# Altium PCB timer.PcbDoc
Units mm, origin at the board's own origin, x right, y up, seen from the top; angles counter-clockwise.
Board outline 237.64 x 122.94 mm, 2 copper layers (Top Layer, Bottom Layer); 21 components, 58 nets, 170 pads, 28 vias.
Unrouted connection lines stored in the file: 1.
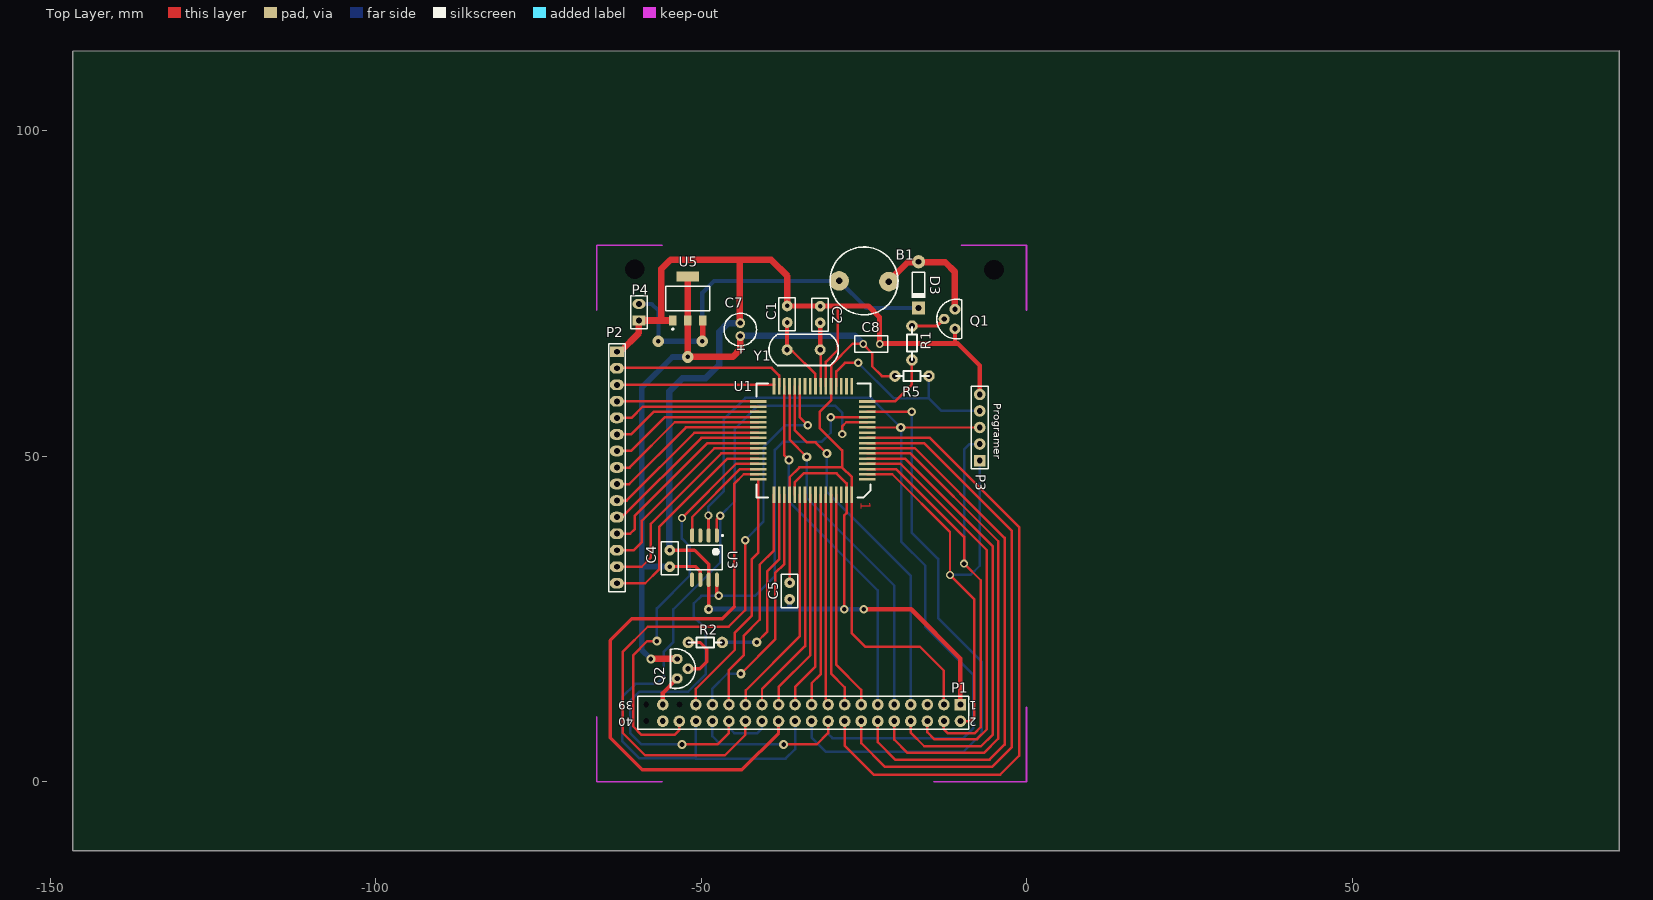
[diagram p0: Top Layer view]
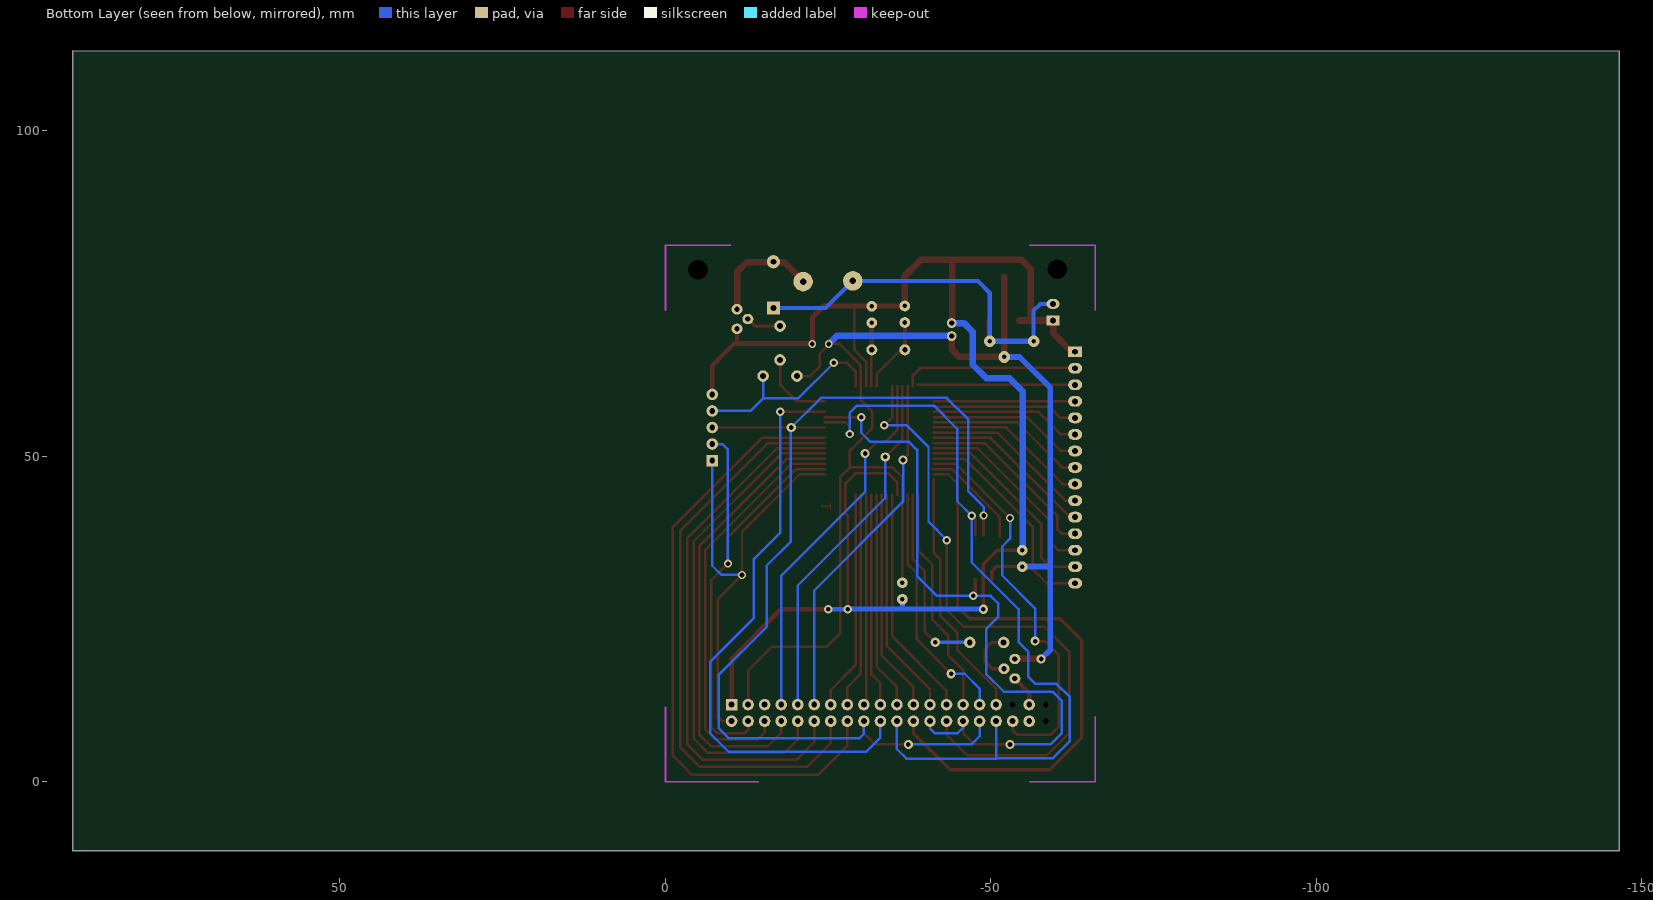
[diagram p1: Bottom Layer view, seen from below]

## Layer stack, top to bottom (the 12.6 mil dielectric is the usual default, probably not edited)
Top Layer: signal copper 0.0356
Dielectric: dielectric 0.32, FR-4, Dk 4.8
Bottom Layer: signal copper 0.0356

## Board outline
91.034,112.344 91.034,-10.592 91.059,-10.566 91.084,-10.566 -146.507,-10.566 -146.507,112.192 -146.558,112.243

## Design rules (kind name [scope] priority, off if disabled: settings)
Clearance [All] p1: gap=0.25
ComponentClearance [All] p1 off: gap=0.254 collisioncheckmode=3 verticalgap=2540 showdistances=FALSE
HoleSize [All] p1: absolutevalues=TRUE maxlimit=5 minlimit=0.025 maxpercent=80.000 minpercent=20.000
PolygonConnect [All] p1: connectstyle=Relief reliefconductorwidth=0.254 reliefentries=4 polygonreliefangle="90 Angle"
RoutingVias [All] p1: holewidth=0.711 width=1.27 viastyle="Through Hole" minholewidth=0.711 minwidth=1.27 maxholewidth=0.711 maxwidth=3
SolderMaskExpansion [All] p1: expansion=0.102
TestPointUsage [All] p1: valid=0 allowmultiple=FALSE
Testpoint [All] p1: side=15 testpointundercomponent=TRUE minsize=1.016 maxsize=2.54 preferedsize=1.524 minholesize=0 maxholesize=1.016 preferedholesize=0.813 testpointgrid=0.025 style=1023 order=0123456789
Width [All] p1: maxlimit=2.54 minlimit=0.254 preferedwidth=0.254 toplayer_minwidth=0.381 toplayer_prefwidth=0.381 bottomlayer_minwidth=0.381 bottomlayer_prefwidth=0.381 minimp=50.000000 maximp=50.000000 favimp=50.000000
17 further rules are at their usual default settings.

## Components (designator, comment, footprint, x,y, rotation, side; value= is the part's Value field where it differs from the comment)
B1 "Speaker" BUZZER -23.698,76.962 r0 top (schematic designator BUZZER1)
C1 "Cap" RAD-0.1#1 -36.779,71.831 r270 top
C2 "Cap" RAD-0.1#1 -31.699,71.78 r270 top
C4 "Cap" RAD-0.1#1 -54.813,34.315 r270 top
C5 "Cap" RAD-0.1#1 -36.398,29.312 r90 top
C7 "Cap Pol1" C100U -44.272,68.834 r270 top
C8 "Cap" RAD-0.1#2 -23.825,67.259 r180 top
D3 "Diode 1N4007" DO-35 -16.586,76.352 r270 top
P1 "TFT LCD Header" HDR2X20 -10.16,11.862 r180 top
P2 "Header 15" HDR1X15 -62.941,66.065 r270 top
P3 "Programer Header" HDR1X5 -7.188,49.352 r90 top
P4 "input" HDR1X2 -59.538,70.869 r90 top
Q1 "2N3904" TO92B -10.998,71.095 r90 top
Q2 "2N3906" TO92B -53.67,17.374 r270 top
R1 "Res1" Res0.125W -17.602,67.412 r90 top
R2 "Res1" Res0.125W -49.352,21.412 r0 top
R5 "Res1" Res0.125W -17.602,62.332 r180 top
U1 "ATmega64L-8AI" "ATMEL TQFP64" -32.842,52.451 r180 top
U3 "AT45DB161D-SU" 8S2_N -49.479,34.442 r270 top
U5 "REG1117-3.3" ZZ311 -52.045,74.244 r0 top
Y1 "" XTAL -34.239,66.37 r0 top

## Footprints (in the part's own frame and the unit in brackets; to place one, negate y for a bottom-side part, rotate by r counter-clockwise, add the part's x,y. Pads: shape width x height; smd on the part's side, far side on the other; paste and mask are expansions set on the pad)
8S2_N [mm] "SOP, 8-Leads, Body 5.3x5.3mm, Pitch 1.27mm, IPC Medium Density"
  oval 2.2x0.6 smd: 1(-3.4,1.905) 2(-3.4,0.635) 3(-3.4,-0.635) 4(-3.4,-1.905) 5(3.4,-1.905) 6(3.4,-0.635) 7(3.4,0.635) 8(3.4,1.905)
  silkscreen extent -3.52,-2.75 1.9,2.88, body extent -2.73,-2.75 2.73,2.75, height 2.03
"ATMEL TQFP64" [mm]
  rect 2.54x0.406 smd: 1(-8.366,5.982) 2(-8.366,5.194) 3(-8.366,4.407) 4(-8.366,3.594) 5(-8.366,2.807) 6(-8.366,1.994) 7(-8.366,1.206) 8(-8.366,0.419) 9(-8.366,-0.394) 10(-8.366,-1.181) 11(-8.366,-1.994) 12(-8.366,-2.781) 13(-8.366,-3.569) 14(-8.366,-4.382) 15(-8.366,-5.169) 16(-8.366,-5.982) 33(8.348,-5.982) 34(8.348,-5.169) 35(8.348,-4.382) 36(8.348,-3.569) 37(8.348,-2.781) 38(8.348,-1.994) 39(8.348,-1.181) 40(8.348,-0.394) 41(8.348,0.419) 42(8.348,1.206) 43(8.366,2) 44(8.348,2.807) 45(8.348,3.594) 46(8.348,4.407) 47(8.348,5.194) 48(8.348,5.982)
  rect 0.406x2.54 smd: 17(-6.003,-8.344) 18(-5.191,-8.344) 19(-4.403,-8.344) 20(-3.616,-8.344) 21(-2.803,-8.344) 22(-2.016,-8.344) 23(-1.203,-8.344) 24(-0.415,-8.344) 25(0.372,-8.344) 26(1.185,-8.344) 27(1.972,-8.344) 28(2.785,-8.344) 29(3.572,-8.344) 30(4.36,-8.344) 31(5.173,-8.344) 32(5.96,-8.344) 49(5.96,8.344) 50(5.173,8.344) 51(4.36,8.344) 52(3.572,8.344) 53(2.785,8.344) 54(1.972,8.344) 55(1.185,8.344) 56(0.372,8.344) 57(-0.415,8.344) 58(-1.203,8.344) 59(-2.016,8.344) 60(-2.803,8.344) 61(-3.616,8.344) 62(-4.403,8.344) 63(-5.191,8.344) 64(-6.003,8.344)
  silkscreen extent -8.87,-8.75 8.65,8.78
BUZZER [mm]
  round 3 hole 1: 1(-5.08,0) 2(2.54,-0.127)
  silkscreen extent -6.47,-5.21 3.94,5.21
C100U [mm]
  round 1.5 hole 0.8: 1(0.36,0.3) 2(-1.64,0.3)
  silkscreen extent -3.14,-2.2 1.86,2.8
DO-35 [mm] "Diode, Axial; Body 3.8 x 1.9 mm (LxDia. max), Lead Dia. 0.53 mm (max)"
  round 2.032 hole 0.9: 1(-3.55,0)
  rect 2.032x2.032 hole 0.9: 2(3.55,0)
  silkscreen extent -1.95,-0.95 2.05,0.95
HDR1X2 [mm] "Connector; Header; 2 Position"
  rect 1.5x2 hole 0.9: 1(0,0)
  oval 1.5x2 hole 0.9: 2(2.54,0)
  silkscreen extent -1.27,-1.27 3.81,1.27
HDR1X5 [mil] "Connector; Header; 5 Position"
  rect 70x70 hole 35.43: 1(0,0)
  round 70 hole 35.43: 2(100,0) 3(200,0) 4(300,0) 5(400,0)
  silkscreen extent -50,-50 450,50
HDR1X15 [mil] "Connector; Header; 15 Position"
  rect 65x85 hole 35.43: 1(0,0)
  oval 65x85 hole 35.43: 2(100,0) 3(200,0) 4(300,0) 5(400,0) 6(500,0) 7(600,0) 8(700,0) 9(800,0) 10(900,0) 11(1000,0) 12(1100,0) 13(1200,0) 14(1300,0) 15(1400,0)
  silkscreen extent -50,-50 1450,50
HDR2X20 [mil] "Connector; Header; 20x2 Position"
  rect 70x70 hole 35.43: 1(0,0)
  round 70 hole 35.43: 2(0,100) 3(100,0) 4(100,100) 5(200,0) 6(200,100) 7(300,0) 8(300,100) 9(400,0) 10(400,100) 11(500,0) 12(500,100) 13(600,0) 14(600,100) 15(700,0) 16(700,100) 17(800,0) 18(800,100) 19(900,0) 20(900,100) 21(1000,0) 22(1000,100) 23(1100,0) 24(1100,100) 25(1200,0) 26(1200,100) 27(1300,0) 28(1300,100) 29(1400,0) 30(1400,100) 31(1500,0) 32(1500,100) 33(1600,0) 34(1600,100) 36(1700,100) 37(1800,0) 38(1800,100)
  round 0 hole 35.43: 35(1700,0) 39(1900,0) 40(1900,100)
  silkscreen extent -50,-50 1950,150
RAD-0.1#1 [mil] "Indicating Instrument; 2 Leads"
  round 65 hole 27.56: 1(-50,0) 2(50,0)
  silkscreen extent -100,-50 100,50
RAD-0.1#2 [mil] "Indicating Instrument; 2 Leads"
  round 47.24 hole 27.56: 1(-50,0) 2(50,0)
  silkscreen extent -100,-50 100,50
Res0.125W [mm]
  round 1.778 hole 0.9: 1(-2.6,0) 2(2.6,0)
  silkscreen extent -2.6,-0.76 2.48,0.76
TO92B [mm]
  oval 1.6x1.7 hole 0.8: 1(-1.5,0) 2(0,1.651) 3(1.5,0)
  silkscreen extent -3.05,-1.06 3.05,2.79
XTAL [mm]
  round 1.7 hole 0.8: 1(-2.54,0) 2(2.54,0)
  silkscreen extent -5.33,-2.41 5.33,2.41
ZZ311 [mm] "SOT-223/SC-73; 4 Leads; Body 6.7 x 7.3 mm, inc. leads (LxW max)"
  rect 1.1x1.55 smd: 1(-2.3,-3.375) 2(0,-3.375) 3(2.3,-3.375)
  rect 3.45x1.55 smd: 4(0,3.375)
  silkscreen extent -3.35,-4.82 3.35,1.85

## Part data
B1: "Loudspeaker"
C1 C2 C4 C5 C8: "Capacitor"
C7: "Polarized Capacitor (Radial)"
D3: "1 Amp General Purpose Rectifier"
P1: library part "Header 20X2", "Header, 20-Pin, Dual row"
P2: "Header, 15-Pin"
P3: library part "Header 5", "Header, 5-Pin"
P4: library part "Header 2", "Header, 2-Pin"
Q1: library part BC817-25, "NPN General Purpose Amplifier"
Q2: "PNP General Purpose Amplifier"
R1 R2 R5: "Resistor"
U1: "8-Bit AVR Microcontroller with 64K Bytes of In-System Programmable Flash Memory"
U5: library part LF33CV, "Very Low Drop Voltage Regulator with Inhibit"
Y1: library part XTAL, "Crystal Oscillator"

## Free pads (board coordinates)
  round 0 hole 3: 0(-60.173,78.715) 0(-5,78.664)

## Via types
v1: diameter 1.27, hole 0.711, Top Layer to Bottom Layer, 14 vias
v2: diameter 1.4, hole 0.711, Top Layer to Bottom Layer, 11 vias
v3: diameter 1.8, hole 0.711, Top Layer to Bottom Layer, 3 vias

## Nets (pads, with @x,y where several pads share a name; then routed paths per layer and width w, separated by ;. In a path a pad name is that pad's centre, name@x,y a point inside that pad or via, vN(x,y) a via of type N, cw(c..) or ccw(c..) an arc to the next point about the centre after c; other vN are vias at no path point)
BD0: P1.2 P3.1 U1.2 | length 70
  Top Layer w0.381: U1.2 -20.638,47.257 -11.76,38.379 v1(-11.76,31.775) -8.052,28.067 -8.052,9.982 -8.712,9.322 P1.2
  Bottom Layer w0.381: v1(-11.76,31.775) -8.611,31.775 -7.188,33.198 P3.1
BD1: P1.4 P3.2 U1.3 | length 77.3
  Top Layer w0.381: U1.3 -20.028,48.044 -9.601,37.617 v1(-9.601,33.528) -7.036,30.963 -7.036,8.407 -7.95,7.493 -12.141,7.493 -12.7,8.052 P1.4
  Bottom Layer w0.381: v1(-9.601,33.528) -9.601,51.029 -8.738,51.892 P3.2
BD2: P1.6 U1.4 | length 63.3
  Top Layer w0.381: U1.4 -19.368,48.857 -6.121,35.611 -6.121,8.052 -7.595,6.579 -14.199,6.579 -15.24,7.62 P1.6
BD3: P1.8 U1.5 | length 69.8
  Top Layer w0.381: U1.5 -18.681,49.644 -5.182,36.144 -5.182,7.29 -7.01,5.461 -15.723,5.461 -17.78,7.518 P1.8
BD4: P1.10 U1.6 | length 76.6
  Top Layer w0.381: U1.6 -17.843,50.457 -4.343,36.957 -4.343,6.655 -6.553,4.445 -18.288,4.445 -20.32,6.477 P1.10
BD5: P1.12 U1.7 | length 83.3
  Top Layer w0.381: U1.7 -17.158,51.245 -3.378,37.465 -3.378,5.715 -5.664,3.429 -20.193,3.429 -22.86,6.096 P1.12
BD6: P1.14 U1.8 | length 90.2
  Top Layer w0.381: P1.14 -25.4,5.944 -21.793,2.337 -5.258,2.337 -2.311,5.283 -2.311,38.583 -15.761,52.032 U1.8
BD7: P1.16 U1.9 | length 97.7
  Top Layer w0.381: P1.16 -27.94,5.563 -23.495,1.118 -4.039,1.118 -1.143,4.013 -1.143,39.141 -14.847,52.845 U1.9
BD8: P1.13 U1.61 | length 33.8
  Top Layer w0.381: U1.61 -29.226,17.949 -25.4,14.122 P1.13
BD9: P1.15 U1.60 | length 33.1
  Top Layer w0.381: U1.60 -30.039,16.628 -27.94,14.529 P1.15
BD10: P1.17 U1.59 | length 32.4
  Top Layer w0.381: P1.17@-30.826,11.709 U1.59
BD11: P1.19 U1.58 | length 32.8
  Top Layer w0.381: P1.19 -33.02,15.138 -31.639,16.519 U1.58
BD12: P1.21 U1.57 | length 33.5
  Top Layer w0.381: P1.21 -35.56,14.554 -32.427,17.687 U1.57
BD13: P1.23 U1.56 | length 34.3
  Top Layer w0.381: P1.23 -38.1,14.554 -33.214,19.44 U1.56
BD14: P1.25 U1.55 | length 35
  Top Layer w0.381: P1.25 -40.64,14.249 -34.027,20.862 U1.55
BD15: P1.27 U1.54 | length 34.9
  Top Layer w0.381: P1.27@-43.129,12.624 -43.129,14.072 -34.814,22.387 U1.54
BUZZER: R1.1 U1.16 | length 11.7
  Top Layer w0.381: U1.16 -20.231,58.433 -17.602,61.062 R1.1
DIN: P1.22 P1.34 U1.12 U3.1 | length 125.6
  Top Layer w0.381: U3.1 -47.574,40.361 v1(-47.041,40.894) ; v1(-28.296,53.416) -28.296,54.635 -27.699,55.232 U1.12
  Bottom Layer w0.381: -50.825,3.607 -59.436,3.607 -62.128,6.299 -62.128,13.005 -60.096,15.037 -56.82,15.037 -55.753,16.104 -55.753,19.964 -54.254,21.463 -54.254,26.518 -47.041,33.731 v1(-47.041,40.894) -44.831,43.104 -44.831,54.204 -41.25,57.785 -29.413,57.785 -28.296,56.667 v1(-28.296,53.416) ; P1.34 -50.8,3.556 -37.008,3.556 -35.56,5.004 P1.22
F_CS: P1.31 U1.51 | length 38
  Top Layer w0.381: v2(-43.891,16.612) -38.633,21.869 -38.633,32.055 -37.202,33.486 U1.51
  Bottom Layer w0.381: P1.31 -48.26,14.326 -45.974,16.612 v2(-43.891,16.612)
F_HOLD: P1.40
F_WP: P1.38
FLASH_CS: U1.46 U3.4 | length 16.4
  Top Layer w0.381: U3.4@-51.384,37.643 U3.4 -51.384,40.64 -43.993,48.031 U1.46@-41.072,48.031
GND: C1.1 C2.1 C4.1 C5.1 C7.2 C8.1 P1.1 P2.1 P3.5 P4.1 Q1.1 U1.22 U1.53 U1.63 U3.7 U5.1 | length 247.3
  Top Layer w0.381: U1.53@-35.649,44.107 U1.53 -35.627,46.008 -34.265,47.371 -29.185,47.371 -27.651,45.838 U1.63 -27.651,41.284 -27.991,40.945 v1(-27.991,26.518) ; U1.22 -30.826,64.5 -29.007,66.319 -29.007,73.076
  Top Layer w0.508: C4.1 -51.003,35.585 -48.844,33.426 U3.7 v2(-48.844,26.518) ; -44.044,80.213 -44.023,80.193
  Top Layer w0.635: -11.024,67.335 -10.998,67.361 Q1.1
  Top Layer w0.7: v1(-25.019,26.518) -17.729,26.518 -10.16,18.948 P1.1 ; C8.1@-22.581,67.335 -10.566,67.335 -7.188,63.957 P3.5
  Top Layer w0.8: C1.1@-36.728,73.076 -24.282,73.076 -22.581,71.374 C8.1@-22.581,67.335
  Top Layer w1: P2.1@-62.433,66.065 -59.538,68.961 P4.1 ; P4.1@-59.56,70.869 P4.1 ; U5.1 -56.109,70.869 ; C7.2@-44.023,70.474 -44.023,80.193 -44.044,80.213 ; C1.1@-36.728,73.076 -36.728,77.699 -39.243,80.213 -44.044,80.213 ; P4.1 -56.109,70.869 ; -56.109,70.869 -56.109,78.791 -54.686,80.213 -44.044,80.213
  Bottom Layer w0.635: v1(-27.991,26.518) v1(-25.019,26.518)
  Bottom Layer w0.762: v2(-48.844,26.518) v1(-27.991,26.518) ; -36.398,26.543 C5.1
  Bottom Layer w1: C4.1@-54.864,35.585 -54.864,59.995 -52.857,62.001 -49.301,62.001 -47.219,64.084 -47.219,69.113 -45.858,70.474 C7.2
LCD_BL: R2.2 U1.50 | length 29.4
  Top Layer w0.381: v2(-41.453,21.438) -39.853,23.038 -39.853,32.334 -38.015,34.172 U1.50
  Bottom Layer w0.508: R2.2@-46.752,21.438 v2(-41.453,21.438)
LCD_CS: P1.29 U1.49 | length 35.1
  Top Layer w0.381: P1.29 -45.72,17.17 -43.434,19.456 -43.434,22.454 -40.996,24.892 -40.996,33.35 -38.802,35.544 U1.49
LCD_RESET: P1.33 U1.48 | length 38.6
  Top Layer w0.381: P1.33 -50.8,14.3 -44.806,20.295 -44.806,22.911 -42.189,25.527 -42.189,34.214 -41.19,35.213 U1.48
NetB1_2: B1.2 D3.1 Q1.3 | length 17.8
  Top Layer w1: B1.2@-21.209,76.886 -18.263,79.832 -12.497,79.832 -10.998,78.334 Q1.3
NetP1_37: P1.37 Q2.3 | length 4.9
  Top Layer w0.635: P1.37 -55.88,13.664 Q2.3
NetQ1_2: Q1.2 R1.2 | length 5.4
  Top Layer w0.508: R1.2 -13.767,70.012 Q1.2@-12.649,71.129
NetQ2_2: Q2.2 R2.1 | length 8.5
  Top Layer w0.508: Q2.2 -50.19,17.374 -49.124,18.44 -49.124,20.371 -50.165,21.412 R2.1
OUT: P1.26 P1.30 U1.13 U3.8 | length 110.6
  Top Layer w0.381: v2(-52.934,5.74) -47.473,5.74 -45.72,7.493 P1.30 ; v1@-47.574,28.854 v1(-47.295,28.575) ; P1.26@-41.123,9.322 P1.26 ; v1(-30.074,56.02) U1.13
  Top Layer w0.508: v1@-47.574,28.854 U3.8
  Bottom Layer w0.381: v2@-52.883,5.74 v2(-52.934,5.74) -59.157,5.74 -60.909,7.493 -60.909,12.421 -59.461,13.868 -51.968,13.868 -49.251,16.586 -49.251,23.495 -51.105,25.349 -51.105,27.432 -49.962,28.575 v1(-47.295,28.575) -41.723,28.575 -38.659,31.639 -38.659,51.003 -37.44,52.222 -31.471,52.222 -30.074,53.619 v1(-30.074,56.02) ; P1.30 -45.72,8.306 -44.907,7.493 -41.351,7.493 -40.64,8.204 P1.26
PA.7: P2.15 U1.44 | length 33
  Top Layer w0.381: P2.15@-62.433,30.505 -58.572,30.505 -56.439,32.639 -56.439,39.141 -45.936,49.644 U1.44
PC.0: P2.6 U1.35 | length 22.7
  Top Layer w0.381: P2.6@-62.433,53.365 -60.757,53.365 -57.289,56.833 U1.35
PC.1: P2.7 U1.36 | length 23.4
  Top Layer w0.381: P2.7@-62.433,50.825 -60.757,50.825 -55.562,56.02 U1.36
PC.2: P2.8 U1.37 | length 24.1
  Top Layer w0.381: P2.8@-62.433,48.285 -60.985,48.285 -54.039,55.232 U1.37
PC.3: P2.9 U1.38 | length 24.8
  Top Layer w0.381: P2.9@-62.433,45.745 -61.036,45.745 -52.337,54.445 U1.38
PC.4: P2.10 U1.39 | length 25.6
  Top Layer w0.381: P2.10@-62.433,43.205 -61.443,43.205 -51.016,53.632 U1.39
PC.5: P2.11 U1.40 | length 26.4
  Top Layer w0.381: P2.11@-62.433,40.665 -62.281,40.513 -49.949,52.845 U1.40
PC.6: P2.12 U1.41 | length 28.2
  Top Layer w0.381: P2.12@-62.433,38.125 -60.884,38.125 -60.173,38.837 -60.173,40.894 -49.035,52.032 U1.41
PC.7: P2.13 U1.42 | length 29.6
  Top Layer w0.381: P2.13@-62.433,35.585 -60.325,35.585 -59.08,36.83 -59.08,40.107 -47.942,51.245 U1.42
PD.6: P2.2 U1.31 | length 26.6
  Top Layer w0.381: P2.2@-62.433,63.602 -39.167,63.602 -38.015,62.45 U1.31
PD.7: P2.3 U1.32 | length 23.7
  Top Layer w0.381: P2.3@-62.484,61.024 U1.32@-38.777,61.024
PENIRQ: P1.28 U1.27 | length 98.6
  Top Layer w0.381: v1(-43.231,37.109) -43.231,26.365 -45.771,23.825 -58.191,23.825 -62.052,19.964 -62.052,7.544 -58.598,4.089 -46.33,4.089 -43.18,7.239 P1.28 ; U1.27 -34.814,55.972 v1(-33.604,54.762)
  Bottom Layer w0.381: v1@-43.282,37.109 -40.411,39.98 -40.411,51.435 -37.084,54.762 v1(-33.604,54.762)
PG.0: P2.4 U1.33 | length 21.3
  Top Layer w0.381: P2.4@-62.484,58.433 U1.33
PG.1: P2.5 U1.34 | length 22
  Top Layer w0.381: P2.5@-62.433,55.905 -60.706,55.905 -58.991,57.62 U1.34
PG.2: P2.14 U1.43 | length 31.5
  Top Layer w0.381: P2.14@-62.433,33.045 -59.106,33.045 -57.709,34.442 -57.709,39.649 -46.907,50.451 U1.43
RD: P1.11 U1.30 | length 54.9
  Top Layer w0.381: U1.30 -37.202,50.14 v2(-36.499,49.437)
  Bottom Layer w0.381: v2(-36.499,49.437) -36.499,43.052 -22.86,29.413 P1.11
RESET: P3.4 R5.1 U1.20 | length 31.4
  Top Layer w0.381: U1.20 -29.226,63.052 -27.915,64.364 v1(-25.857,64.364)
  Bottom Layer w0.381: v1@-25.87,64.376 v1(-25.857,64.364) -20.387,58.893 -15.002,58.893 ; R5.1 -15.002,58.893 ; P3.4 -13.081,56.972 -15.002,58.893
RS: P1.7 U1.28 | length 57.1
  Top Layer w0.381: U1.28 -35.627,54.042 -33.731,52.146 -32.41,52.146 v2@-30.696,50.432
  Bottom Layer w0.381: v2@-30.683,50.432 -30.683,44.526 -17.78,31.623 P1.7
  other v2: -30.683,50.444
SCK: P1.18 P1.32 P3.3 U1.11 U3.2 | length 165.7
  Top Layer w0.381: U3.2@-48.87,37.868 U3.2 ; v2(-37.313,5.74) -32.233,5.74 -30.48,7.493 P1.18 ; U1.11@-24.486,54.432 v2(-19.329,54.432) P3.3
  Top Layer w0.508: U3.2@-48.87,37.868 v1(-48.87,40.919)
  Bottom Layer w0.381: v1(-48.87,40.919) -48.87,42.291 -46.533,44.628 -46.533,55.651 -43.205,58.979 -23.876,58.979 v2(-19.329,54.432) -19.279,54.381 -19.279,36.932 -15.57,33.223 -15.57,23.8 -8.153,16.383 -8.153,8.255 -9.677,6.731 -29.82,6.731 -30.48,7.391 P1.18 ; P1.32 -48.26,7.01 -46.99,5.74 v2(-37.313,5.74)
SD_CS: P1.36 U1.45 | length 61.5
  Top Layer w0.381: v2(-56.794,21.615) -58.268,21.615 -60.452,19.431 -60.452,8.534 -59.131,7.214 -54.077,7.214 -53.34,7.95 P1.36 ; v1(-52.934,40.538) -44.615,48.857 U1.45
  Bottom Layer w0.381: v2(-56.794,21.615) -56.794,26.645 -51.74,31.699 -51.74,36.17 -52.934,37.363 v1(-52.934,40.538)
T_BUSY: P1.24 U1.47 | length 91.5
  Top Layer w0.381: -44.882,26.873 -44.882,45.822 -43.446,47.257 U1.47
  Top Layer w0.508: -44.882,26.873 -46.711,25.044 -60.63,25.044 -63.957,21.717 -63.957,6.756 -59.055,1.854 -43.739,1.854 -38.1,7.493 P1.24
T_CS: P1.20 U1.14 | length 91.4
  Top Layer w0.381: U1.14 v1(-17.641,56.833)
  Bottom Layer w0.381: P1.20 -33.02,6.807 -30.81,4.597 -9.728,4.597 -6.858,7.468 -6.858,18.415 -13.589,25.146 -13.589,34.239 -17.654,38.304 v1@-17.654,56.82
VCC3: C4.2 C5.2 C7.1 C8.2 P1.3 Q2.1 R5.2 U1.21 U1.52 U1.64 U3.6 U5.2 U5.4 | length 213.6
  Top Layer w0.381: C5.2@-36.414,30.505 -36.414,46.796 -34.9,48.311 -28.346,48.311 ; R5.2 -22.225,62.332 -23.698,63.805 -23.698,65.828 -25.298,67.428 -25.298,67.31 -26.695,67.31 -30.039,63.966 U1.21 -30.039,58.581 -31.75,56.871 -31.75,54.305 -28.346,50.902 -28.346,48.311 ; P1.3 -12.7,17.069 -16.408,20.777 -24.816,20.777 -26.839,22.801 U1.64 -26.839,46.804 -28.346,48.311
  Top Layer w0.508: C4.2@-54.813,33.071 -50.8,33.071 -50.114,32.385 U3.6
  Top Layer w1: v2(-57.71,18.874) Q2.1 ; U5.4 v3(-52.045,65.278) -45.136,65.278 -44.018,66.396 C7.1@-44.018,68.478
  Bottom Layer w0.508: -59.097,33.198 -58.97,33.071
  Bottom Layer w0.889: -58.97,33.071 C4.2@-54.813,33.071 ; v2(-57.71,18.874) -59.097,20.26 -59.097,33.198 -59.097,60.562 -54.381,65.278 v3(-52.045,65.278)
  Bottom Layer w1: C7.1@-44.023,68.555 -26.391,68.555 C8.2
VCC5: B1.1 D3.2 P4.2 U5.3 | length 61.4
  Top Layer w0.635: v3(-49.809,67.691) v3@-49.745,67.756
  Top Layer w0.8: v3@-49.745,67.756 U5.3
  Bottom Layer w0.635: P4.2 -57.585,73.409 -56.566,72.39 v3(-56.566,67.691) v3@-56.566,67.589 ; v3@-49.708,67.793 v3(-49.809,67.691) -49.809,75.133 -48.031,76.911 B1.1@-28.778,76.911 ; B1.1 -24.619,72.802 D3.2
  Bottom Layer w0.8: v3(-56.566,67.691) v3(-49.809,67.691)
WR: P1.9 U1.29 | length 55.6
  Top Layer w0.381: U1.29 -36.414,52.569 v2(-33.769,49.924)
  Bottom Layer w0.381: v2(-33.769,49.924) -33.769,43.599 -20.32,30.15 P1.9
XTAL1: C1.2 U1.24 Y1.1 | length 12.1
  Top Layer w0.381: Y1.1@-36.779,66.142 -35.941,66.142 -32.427,62.628 U1.24
  Top Layer w0.635: Y1.1@-36.779,66.142 C1.2
XTAL2: C2.2 U1.23 Y1.2 | length 9.6
  Top Layer w0.381: U1.23 Y1.2@-31.639,66.049
  Top Layer w0.635: Y1.2@-31.699,66.142 C2.2
pads on no net: P1.5 P1.35 P1.39 U1.1 U1.10 U1.15 U1.17 U1.18 U1.19 U1.25 U1.26 U1.62 U3.3 U3.5

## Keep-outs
Keep-Out Layer:
  lines w0.254: -66,10 -66,0 -56,0 ; -66,72.448 -66,82.448 -56,82.448 ; -14.267,0 0,0 0,11.448 ; -10,82.448 0,82.448 0,72.448

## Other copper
Top Layer:
  text "1" at -25.451,43.002 h1.52 r270

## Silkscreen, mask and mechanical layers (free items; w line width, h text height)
Top Overlay:
  text "Programer" at -5.055,58.141 h1.2 r270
